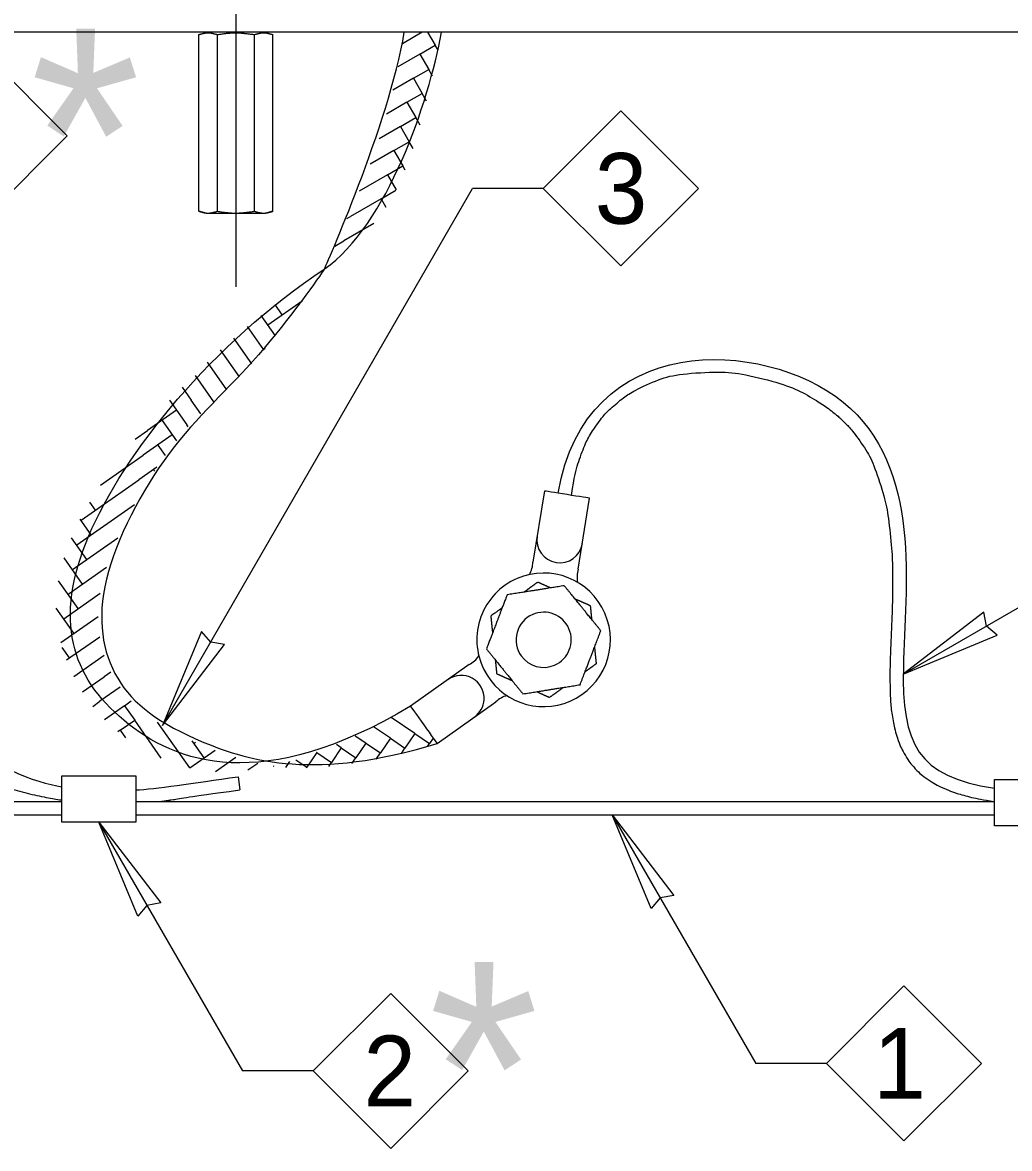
# Model space of a CAD drawing. Extents: x 99862 to 103680, y 99470 to 102076.
# Drawn here: x 101482.3 to 101705.7, y 100247.9 to 100502.7 of the extents above; entities that cross this region are included whole.
import ezdxf

# ---------------------------------------------------------------- set-up
doc = ezdxf.new("R2010")
doc.units = 0
for name, color, linetype in [('Level 1', 7, 'Continuous'), ('Level 10', 7, 'Continuous'), ('Level 11', 7, 'Continuous'), ('Level 13', 7, 'Continuous'), ('Level 15', 7, 'Continuous'), ('Level 20', 7, 'Continuous'), ('Level 3', 7, 'Continuous'), ('Level 9', 7, 'Continuous')]:
    doc.layers.add(name, color=color, linetype=linetype)

msp = doc.modelspace()

# ---------------------------------------------------------------- linework, layer by layer
at = {"layer": 'Level 1'}
msp.add_line((102062.21, 100500.54), (101248.49, 100500.54), dxfattribs=at)
at = {"layer": 'Level 10'}
for p, q in [((101522.21, 100500.01), (101524.09, 100500.54)), ((101522.21, 100460.03), (101522.21, 100500.01)), ((101526.4, 100460.03), (101526.4, 100500.01)), ((101534.78, 100460.03), (101534.78, 100500.01)), ((101537.09, 100500.54), (101538.98, 100500.01)), ((101538.98, 100460.03), (101538.98, 100500.01)), ((101524.09, 100459.5), (101522.21, 100460.03)), ((101524.09, 100459.5), (101522.59, 100459.92)), ((101537.09, 100459.5), (101524.09, 100459.5)), ((101538.98, 100460.03), (101537.09, 100459.5)), ((101597.75, 100368.79), (101597.75, 100368.79)), ((101602.72, 100357.32), (101602.72, 100357.32))]:
    msp.add_line(p, q, dxfattribs=at)
for start, end in [(113.4171, 215.8268), (293.4171, 113.4171), (215.8268, 293.4171)]:
    msp.add_arc((101600.24, 100363.05), 6.25, start, end, dxfattribs=at)
for points in [[(101522.21, 100500.01), (101523.6, 100500.44), (101525, 100500.43), (101526.4, 100500.01)], [(101526.4, 100500.01), (101529.18, 100500.46), (101532.01, 100500.41), (101534.78, 100500.01)], [(101534.78, 100500.01), (101536.18, 100500.44), (101537.58, 100500.43), (101538.98, 100500.01)], [(101522.21, 100460.03), (101523.6, 100459.6), (101525, 100459.61), (101526.4, 100460.03)], [(101526.4, 100460.03), (101529.18, 100459.58), (101532.01, 100459.63), (101534.78, 100460.03)], [(101534.78, 100460.03), (101536.18, 100459.6), (101537.58, 100459.61), (101538.98, 100460.03)], [(101598.91, 100376.09), (101597.87, 100375.34), (101596.82, 100374.58), (101595.78, 100373.83)], [(101601.79, 100374.79), (101600.83, 100375.22), (101599.87, 100375.65), (101598.91, 100376.09)], [(101604.92, 100375.29), (101600.61, 100374.6), (101596.29, 100373.91), (101591.98, 100373.23)], [(101613.18, 100365.12), (101610.42, 100368.51), (101607.67, 100371.9), (101604.92, 100375.29)], [(101591.98, 100373.23), (101590.59, 100369.6), (101589.2, 100365.96), (101587.3, 100360.99)], [(101610.86, 100370.72), (101609.69, 100371.25), (101608.52, 100371.77), (101607.35, 100372.3)], [(101590.85, 100370.27), (101590.38, 100369.93), (101589.91, 100369.59), (101588.28, 100368.42)], [(101588.28, 100368.42), (101588.41, 100367.14), (101588.54, 100365.86), (101588.67, 100364.58)], [(101611.18, 100367.57), (101611.07, 100368.62), (101610.97, 100369.67), (101610.86, 100370.72)], [(101608.49, 100352.88), (101610.06, 100356.96), (101611.62, 100361.04), (101613.18, 100365.12)], [(101587.3, 100360.99), (101590.05, 100357.6), (101592.8, 100354.21), (101595.55, 100350.81)], [(101612.19, 100357.69), (101612.06, 100358.96), (101611.93, 100360.24), (101611.8, 100361.52)], [(101589.29, 100358.53), (101589.4, 100357.48), (101589.5, 100356.43), (101589.61, 100355.38)], [(101609.62, 100355.83), (101610.48, 100356.45), (101611.33, 100357.07), (101612.19, 100357.69)], [(101589.61, 100355.38), (101590.78, 100354.86), (101591.96, 100354.33), (101593.13, 100353.8)], [(101595.55, 100350.81), (101599.87, 100351.5), (101604.18, 100352.19), (101608.49, 100352.88)], [(101598.68, 100351.31), (101599.64, 100350.88), (101600.6, 100350.45), (101601.57, 100350.02)], [(101601.57, 100350.02), (101602.61, 100350.77), (101603.65, 100351.52), (101604.69, 100352.27)]]:
    msp.add_open_spline(points, degree=2, dxfattribs=at)
at = {"layer": 'Level 11'}
for p, q in [((101572.75, 100500.54), (101568.26, 100497.95)), ((101573.99, 100500.54), (101575.68, 100497.61)), ((101572.22, 100495.61), (101575.68, 100497.61)), ((101576.35, 100496.46), (101575.68, 100497.61)), ((101572.22, 100495.61), (101567.26, 100492.75)), ((101572.22, 100495.61), (101574.22, 100492.15)), ((101570.75, 100490.15), (101574.22, 100492.15)), ((101575.11, 100490.6), (101574.22, 100492.15)), ((101570.75, 100490.15), (101566.08, 100487.45)), ((101570.75, 100490.15), (101572.75, 100486.69)), ((101569.29, 100484.69), (101572.75, 100486.69)), ((101573.76, 100484.93), (101572.75, 100486.69)), ((101569.29, 100484.69), (101564.68, 100482.03)), ((101569.29, 100484.69), (101571.29, 100481.22)), ((101567.83, 100479.22), (101571.29, 100481.22)), ((101572.29, 100479.48), (101571.29, 100481.22)), ((101567.83, 100479.22), (101563.02, 100476.45)), ((101567.83, 100479.22), (101569.83, 100475.76)), ((101567.83, 100479.22), (101567.83, 100479.22)), ((101566.36, 100473.76), (101569.83, 100475.76)), ((101570.7, 100474.24), (101569.83, 100475.76)), ((101566.36, 100473.76), (101561, 100470.66)), ((101566.36, 100473.76), (101568.36, 100470.29)), ((101564.9, 100468.29), (101558.51, 100464.61)), ((101564.9, 100468.29), (101568.36, 100470.29)), ((101564.9, 100468.29), (101566.86, 100464.89)), ((101568.93, 100469.3), (101568.36, 100470.29)), ((101563.43, 100462.83), (101556.51, 100458.83)), ((101563.43, 100462.83), (101566.8, 100464.77)), ((101563.43, 100462.83), (101564.51, 100460.97)), ((101555.73, 100458.38), (101556.51, 100458.83)), ((101561.78, 100457.26), (101555.04, 100453.37)), ((101552.95, 100452.16), (101555.04, 100453.37)), ((101537.81, 100434.33), (101545.56, 100439.75)), ((101541.09, 100436.63), (101539.46, 100438.96)), ((101539.54, 100431.87), (101536.31, 100436.48)), ((101536.9, 100428.66), (101533.19, 100433.95)), ((101534.2, 100425.54), (101530.15, 100431.33)), ((101531.43, 100422.53), (101527.12, 100428.68)), ((101536.83, 100428.76), (101537.19, 100429.02)), ((101528.57, 100419.64), (101524.17, 100425.91)), ((101525.6, 100416.91), (101521.43, 100422.86)), ((101518.4, 100420.22), (101520.45, 100417.29)), ((101515.56, 100417.3), (101519.47, 100411.72)), ((101522.62, 100414.19), (101520.45, 100417.29)), ((101517.17, 100414.99), (101510.62, 100410.41)), ((101517.17, 100414.99), (101517.17, 100414.99)), ((101513.89, 100412.7), (101517.11, 100408.1)), ((101519.79, 100411.25), (101519.46, 100411.72)), ((101507.79, 100408.43), (101510.62, 100410.41)), ((101516.19, 100409.42), (101509.64, 100404.84)), ((101512.91, 100407.12), (101514.56, 100404.77)), ((101499.94, 100398.04), (101509.64, 100404.84)), ((101512.72, 100402.11), (101508.65, 100399.26)), ((101511.92, 100401.55), (101512.14, 100401.25)), ((101495.55, 100390.09), (101508.65, 100399.26)), ((101498.82, 100392.38), (101497.53, 100394.23)), ((101494.56, 100384.52), (101507.61, 100393.65)), ((101497.84, 100386.81), (101495.38, 100390.33)), ((101496.86, 100381.24), (101493.42, 100386.16)), ((101493.58, 100378.95), (101503.85, 100386.14)), ((101495.88, 100375.67), (101491.74, 100381.58)), ((101492.6, 100373.38), (101501.32, 100379.48)), ((101494.89, 100370.1), (101490.46, 100376.43)), ((101491.62, 100367.8), (101499.88, 100373.59)), ((101493.91, 100364.53), (101489.91, 100370.24)), ((101490.94, 100362.45), (101499.38, 100368.36)), ((101492.27, 100358.49), (101499.76, 100363.74)), ((101492.93, 100358.96), (101491.27, 100361.32)), ((101493.92, 100354.76), (101500.78, 100359.57)), ((101502.32, 100355.76), (101500.79, 100354.7)), ((101495.88, 100351.26), (101500.8, 100354.7)), ((101504.36, 100352.31), (101499.81, 100349.13)), ((101498.19, 100347.99), (101499.81, 100349.13)), ((101505.38, 100348.14), (101500.84, 100344.97)), ((101505.38, 100348.14), (101506.91, 100349.21)), ((101505.38, 100348.14), (101507.68, 100344.87)), ((101571.1, 100341.84), (101565.71, 100345.47)), ((101504.4, 100342.57), (101507.68, 100344.87)), ((101513.7, 100336.27), (101507.68, 100344.87)), ((101520.13, 100334.06), (101512.88, 100344.41)), ((101565.55, 100340.76), (101561.73, 100343.33)), ((101504.4, 100342.57), (101503.87, 100342.2)), ((101504.4, 100342.57), (101505.59, 100340.88)), ((101559.99, 100339.68), (101557.62, 100341.28)), ((101565.55, 100340.76), (101563.31, 100337.44)), ((101565.55, 100340.76), (101568.86, 100338.52)), ((101571.1, 100341.84), (101568.86, 100338.52)), ((101571.1, 100341.84), (101574.42, 100339.6)), ((101575.24, 100340.82), (101574.42, 100339.6)), ((101520.13, 100334.06), (101525.88, 100338.08)), ((101523.41, 100336.35), (101520.72, 100340.19)), ((101521.11, 100339.63), (101521.46, 100339.87)), ((101554.44, 100338.6), (101552.21, 100335.28)), ((101554.44, 100338.6), (101553.34, 100339.34)), ((101554.44, 100338.6), (101557.76, 100336.36)), ((101559.99, 100339.68), (101557.76, 100336.36)), ((101559.99, 100339.68), (101559.99, 100339.68)), ((101559.99, 100339.68), (101563.31, 100337.44)), ((101568.04, 100337.31), (101568.86, 100338.52)), ((101573.95, 100338.91), (101574.42, 100339.6)), ((101525.94, 100333.24), (101530.56, 100336.48)), ((101542.69, 100335.48), (101541.81, 100334.18)), ((101544.13, 100335.91), (101546.65, 100334.21)), ((101548.89, 100337.52), (101546.65, 100334.2)), ((101548.89, 100337.52), (101548.86, 100337.54)), ((101548.89, 100337.52), (101552.21, 100335.28)), ((101551.59, 100334.37), (101552.21, 100335.28)), ((101556.85, 100335.02), (101557.76, 100336.36)), ((101562.34, 100336), (101563.31, 100337.44)), ((101535.52, 100335.07), (101533.32, 100333.53)), ((101539.02, 100334.53), (101539.16, 100334.43)), ((101546.56, 100334.07), (101546.65, 100334.21))]:
    msp.add_line(p, q, dxfattribs=at)
for points in [[(101550.6, 100446.92), (101564.85, 100456.96), (101574.22, 100484.54), (101577.12, 100500.54)], [(101550.6, 100446.92), (101550.6, 100446.92), (101565.27, 100479.72), (101568.7, 100500.54)], [(101570.12, 100348.01), (101536.52, 100328.07), (101497.55, 100341.84), (101485.12, 100380.41), (101525.28, 100430.19), (101550.6, 100446.92)], [(101550.6, 100446.92), (101549.67, 100445.53), (101535.61, 100425.48), (101514.9, 100407.72), (101497.83, 100375), (101501.62, 100352.81), (101518.71, 100339.8), (101548.73, 100331.23), (101576.14, 100339.56)]]:
    msp.add_open_spline(points, degree=3, dxfattribs=at)
at = {"layer": 'Level 13'}
for p, q in [((101600.41, 100396.73), (101597.82, 100380.65)), ((101608.06, 100379), (101610.65, 100395.08)), ((101594.23, 100376.91), (101594.23, 100376.91)), ((101583.39, 100357.45), (101570.12, 100348.01)), ((101576.14, 100339.56), (101589.41, 100349)), ((101606.24, 100349.19), (101606.24, 100349.19))]:
    msp.add_line(p, q, dxfattribs=at)
for centre, radius, start, end in [((101603.88, 100385.67), 5.19, 170.8415, 350.8415), ((101591.11, 100380.94), 6.72, 332.2757, 357.5208), ((101614.52, 100377.17), 6.72, 164.1622, 189.4065), ((101600.24, 100363.05), 15.11, 113.4171, 206.4185), ((101600.24, 100363.05), 15.11, 113.4171, 206.4185), ((101600.24, 100363.05), 15.11, 293.4171, 113.4171), ((101580.16, 100363.34), 6.72, 298.7727, 323.9986), ((101600.24, 100363.05), 15.11, 206.4185, 293.4171), ((101600.24, 100363.05), 15.11, 206.4185, 293.4171), ((101581.58, 100349.8), 5.19, 356.4789, 125.4521), ((101581.58, 100349.8), 5.19, 305.4521, 356.4789), ((101593.91, 100344.02), 6.72, 106.8971, 132.1314)]:
    msp.add_arc(centre, radius, start, end, dxfattribs=at)
for centre, major_axis in [((101605.53, 100395.91), (-5.12, 0.83)), ((101573.13, 100343.78), (3.01, -4.22))]:
    msp.add_ellipse(centre, major_axis=major_axis, ratio=0.000026, start_param=3.14156, end_param=6.283152, dxfattribs=at)
at = {"layer": 'Level 15'}
for p, q in [((101530.59, 100650.56), (101530.59, 100442.92)), ((101514.01, 100343.69), (101584.16, 100465.21)), ((101600.16, 100465.21), (101584.16, 100465.21)), ((101681.62, 100355.27), (101727, 100381.48)), ((101615.73, 100323.47), (101648.23, 100267.18)), ((101499.57, 100321.78), (101532.07, 100265.49)), ((101664.23, 100267.18), (101648.23, 100267.18)), ((101548.07, 100265.49), (101532.07, 100265.49))]:
    msp.add_line(p, q, dxfattribs=at)
for points in [[(101681.62, 100355.27), (101702.88, 100364.1), (101700.47, 100366.16), (101699.9, 100369.27)], [(101514.01, 100343.69), (101528.01, 100361.97), (101524.89, 100362.55), (101522.84, 100364.96)], [(101615.73, 100323.47), (101629.73, 100305.2), (101626.62, 100304.62), (101624.56, 100302.21)], [(101499.57, 100321.78), (101513.57, 100303.5), (101510.46, 100302.92), (101508.4, 100300.51)]]:
    msp.add_lwpolyline(points, close=True, dxfattribs=at)
at = {"layer": 'Level 20'}
for points in [[(101474.86, 100494.65), (101492.41, 100477.1), (101474.86, 100459.54), (101457.3, 100477.1)], [(101617.72, 100482.76), (101635.27, 100465.21), (101617.72, 100447.66), (101600.16, 100465.21)], [(101681.78, 100284.74), (101699.33, 100267.18), (101681.78, 100249.63), (101664.23, 100267.18)], [(101565.62, 100247.93), (101583.18, 100265.49), (101565.62, 100283.04), (101548.07, 100265.49)]]:
    msp.add_lwpolyline(points, close=True, dxfattribs=at)
at = {"layer": 'Level 3'}
for points in [[(101491.22, 100332.26), (101507.92, 100332.26), (101507.92, 100321.78), (101491.22, 100321.78)], [(101702.27, 100331.46), (101718.98, 100331.46), (101718.98, 100320.98), (101702.27, 100320.98)]]:
    msp.add_lwpolyline(points, close=True, dxfattribs=at)
at = {"layer": 'Level 9'}
for p, q in [((101531.08, 100332.04), (101531.48, 100329.07)), ((101374.08, 100326.47), (101491.22, 100326.47)), ((101507.92, 100326.47), (101702.27, 100326.47)), ((101374.08, 100323.47), (101491.22, 100323.47)), ((101507.92, 100323.47), (101702.27, 100323.47))]:
    msp.add_line(p, q, dxfattribs=at)
for points in [[(101603.53, 100396.23), (101609.56, 100432.97), (101690.3, 100429.88), (101677.85, 100346.9), (101684.76, 100332.08), (101702.27, 100329.49)], [(101354.05, 100394.56), (101359.84, 100407.91), (101378.24, 100427.09), (101415.54, 100419.63), (101446.81, 100391.19), (101463.97, 100337.01), (101485.2, 100330.82), (101491.22, 100329.81)], [(101606.56, 100395.74), (101607.21, 100400.18), (101607.86, 100402.67), (101609.64, 100407.45), (101610.82, 100409.66), (101613.55, 100413.54), (101615.12, 100415.21), (101618.56, 100418.08), (101620.44, 100419.27), (101626.47, 100422.19), (101631.02, 100423.26), (101640.43, 100423.81), (101645.29, 100423.3), (101654.48, 100420.97), (101658.81, 100419.16), (101663.36, 100416.32), (101664.23, 100415.73), (101665.86, 100414.49), (101666.63, 100413.85), (101668.81, 100411.85), (101670.08, 100410.41), (101673.45, 100405.84), (101675.1, 100402.43), (101677.5, 100395.09), (101678.24, 100391.16), (101679.11, 100383.11), (101679.24, 100378.99), (101679.18, 100370.9), (101679.01, 100366.92), (101678.78, 100361.3), (101678.7, 100359.48), (101678.61, 100355.99), (101678.6, 100354.31), (101678.69, 100349.54), (101678.93, 100346.66), (101679.72, 100342.71), (101680.06, 100341.45), (101680.93, 100339.06), (101681.46, 100337.92), (101682.74, 100335.78), (101683.49, 100334.79), (101685.21, 100332.97), (101686.18, 100332.14), (101688.33, 100330.68), (101689.5, 100330.03), (101692.05, 100328.89), (101693.42, 100328.4), (101697.11, 100327.34), (101699.55, 100326.85), (101702.27, 100326.46)], [(101357.03, 100393.63), (101357.78, 100396.5), (101359.02, 100399.44), (101361.82, 100404.23), (101363.05, 100406.03), (101365.17, 100408.77), (101365.92, 100409.69), (101367.12, 100411.08), (101367.74, 100411.77), (101368.49, 100412.59), (101368.88, 100413), (101369.04, 100413.17), (101369.15, 100413.29), (101369.21, 100413.35), (101370.95, 100415.16), (101372.75, 100416.6), (101376.61, 100418.9), (101378.66, 100419.77), (101383.1, 100420.94), (101385.49, 100421.25), (101389.34, 100421.27), (101390.67, 100421.21), (101392.73, 100421), (101393.78, 100420.86), (101394.85, 100420.69), (101395.57, 100420.56), (101395.93, 100420.49), (101402.24, 100419.23), (101407.93, 100417.21), (101416.13, 100412.91), (101418.81, 100411.27), (101422.75, 100408.48), (101424.05, 100407.5), (101425.98, 100405.94), (101426.94, 100405.15), (101428.05, 100404.18), (101428.53, 100403.76), (101428.84, 100403.47), (101429, 100403.33), (101434.12, 100398.68), (101438.56, 100393.11), (101444.41, 100383.12), (101446.23, 100379.52), (101448.75, 100373.71), (101449.55, 100371.7), (101450.71, 100368.59), (101451.27, 100367), (101451.91, 100365.11), (101452.22, 100364.16), (101452.38, 100363.68), (101452.44, 100363.47), (101452.49, 100363.33), (101452.51, 100363.26), (101453.99, 100358.58), (101455.57, 100354.42), (101459.01, 100347.03), (101460.85, 100343.79), (101464.87, 100338.23), (101467.04, 100335.9), (101470.58, 100333.14), (101471.81, 100332.34), (101473.71, 100331.34), (101474.36, 100331.04), (101475.35, 100330.64), (101475.84, 100330.45), (101476.43, 100330.26), (101476.72, 100330.17), (101476.87, 100330.12), (101476.94, 100330.1), (101476.98, 100330.09), (101477, 100330.08), (101481.74, 100328.7), (101486.08, 100327.67), (101490.44, 100326.9), (101490.83, 100326.83), (101491.22, 100326.77)], [(101507.92, 100329.06), (101512.32, 100329.27), (101520.76, 100330.65), (101531.08, 100332.04)], [(101513.37, 100326.47), (101513.72, 100326.52), (101514.07, 100326.56), (101514.67, 100326.64), (101515.05, 100326.69), (101515.48, 100326.75), (101515.66, 100326.78), (101515.78, 100326.8), (101515.85, 100326.81), (101519.41, 100327.39), (101524.61, 100328.14), (101531.48, 100329.07)]]:
    msp.add_open_spline(points, degree=3, dxfattribs=at)

# ---------------------------------------------------------------- texts
at = {"layer": 'Level 20'}
for s, height, p in [('*', 48, (101484.02, 100453.39)), ('3', 16, (101611.81, 100457.21)), ('*', 48, (101574.19, 100242.1)), ('1', 16, (101674.83, 100259.19)), ('2', 16, (101559.45, 100257.48))]:
    msp.add_text(s, height=height, dxfattribs=at).set_placement(p)

doc.saveas('drawing.dxf')
